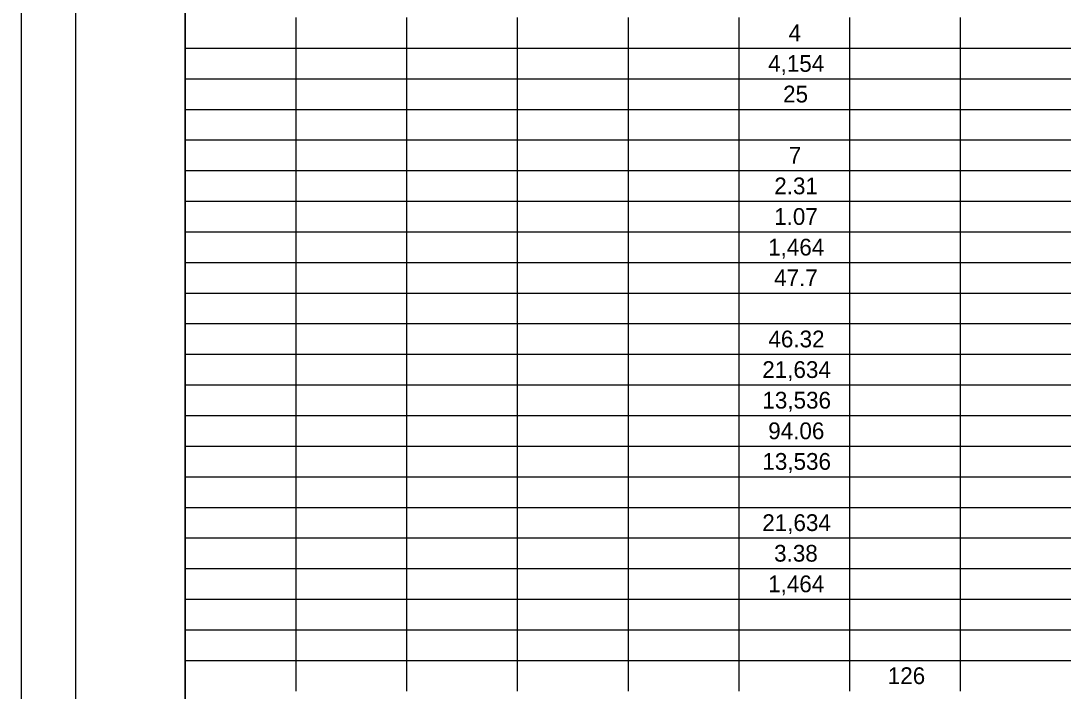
# Model space of a CAD drawing. Extents: x 0 to 34, y 0 to 22.
# Drawn here: x 0 to 9.6, y 9.74 to 15.87 of the extents above; entities that cross this region are included whole.
import ezdxf

# ---------------------------------------------------------------- set-up
doc = ezdxf.new("R2010")
doc.units = 0
for name, color, linetype in [('SH_Border', 7, 'Continuous'), ('SH_Cut_Line', 7, 'Continuous'), ('SH_Text', 7, 'Continuous')]:
    doc.layers.add(name, color=color, linetype=linetype)

msp = doc.modelspace()

# ---------------------------------------------------------------- linework, layer by layer
at = {"layer": 'SH_Border'}
for points in [[(0.5, 21.5), (1.5, 21.5), (1.5, 0.5), (0.5, 0.5)], [(1.5, 21.5), (33.5, 21.5), (33.5, 0.5), (1.5, 0.5)]]:
    msp.add_lwpolyline(points, close=True, dxfattribs=at)
at = {"layer": 'SH_Cut_Line'}
msp.add_lwpolyline([(0, 0), (34, 0), (34, 22), (0, 22)], close=True, dxfattribs=at)
at = {"layer": 'SH_Text'}
for p, q in [((1.5, 15.9), (1.5, 15.62)), ((2.5123, 15.9), (2.5123, 15.62)), ((3.5247, 15.9), (3.5247, 15.62)), ((4.537, 15.9), (4.537, 15.62)), ((5.5494, 15.9), (5.5494, 15.62)), ((6.5617, 15.9), (6.5617, 15.62)), ((7.574, 15.9), (7.574, 15.62)), ((8.5864, 15.9), (8.5864, 15.62)), ((1.5, 15.62), (2.5123, 15.62)), ((1.5, 15.62), (1.5, 15.34)), ((2.5123, 15.62), (3.5247, 15.62)), ((2.5123, 15.62), (2.5123, 15.34)), ((3.5247, 15.62), (4.537, 15.62)), ((3.5247, 15.62), (3.5247, 15.34)), ((4.537, 15.62), (5.5494, 15.62)), ((4.537, 15.62), (4.537, 15.34)), ((5.5494, 15.62), (6.5617, 15.62)), ((5.5494, 15.62), (5.5494, 15.34)), ((6.5617, 15.62), (7.574, 15.62)), ((6.5617, 15.62), (6.5617, 15.34)), ((7.574, 15.62), (8.5864, 15.62)), ((7.574, 15.62), (7.574, 15.34)), ((8.5864, 15.62), (9.5987, 15.62)), ((8.5864, 15.62), (8.5864, 15.34)), ((1.5, 15.34), (2.5123, 15.34)), ((1.5, 15.34), (1.5, 14.78)), ((2.5123, 15.34), (3.5247, 15.34)), ((2.5123, 15.34), (2.5123, 14.78)), ((3.5247, 15.34), (4.537, 15.34)), ((3.5247, 15.34), (3.5247, 14.78)), ((4.537, 15.34), (5.5494, 15.34)), ((4.537, 15.34), (4.537, 14.78)), ((5.5494, 15.34), (6.5617, 15.34)), ((5.5494, 15.34), (5.5494, 14.78)), ((6.5617, 15.34), (7.574, 15.34)), ((6.5617, 15.34), (6.5617, 14.78)), ((7.574, 15.34), (8.5864, 15.34)), ((7.574, 15.34), (7.574, 14.78)), ((8.5864, 15.34), (9.5987, 15.34)), ((8.5864, 15.34), (8.5864, 14.78)), ((1.5, 15.06), (2.5123, 15.06)), ((2.5123, 15.06), (3.5247, 15.06)), ((3.5247, 15.06), (4.537, 15.06)), ((4.537, 15.06), (5.5494, 15.06)), ((5.5494, 15.06), (6.5617, 15.06)), ((6.5617, 15.06), (7.574, 15.06)), ((7.574, 15.06), (8.5864, 15.06)), ((8.5864, 15.06), (9.5987, 15.06)), ((1.5, 14.78), (2.5123, 14.78)), ((1.5, 14.78), (1.5, 14.5)), ((2.5123, 14.78), (3.5247, 14.78)), ((2.5123, 14.78), (2.5123, 14.5)), ((3.5247, 14.78), (4.537, 14.78)), ((3.5247, 14.78), (3.5247, 14.5)), ((4.537, 14.78), (5.5494, 14.78)), ((4.537, 14.78), (4.537, 14.5)), ((5.5494, 14.78), (6.5617, 14.78)), ((5.5494, 14.78), (5.5494, 14.5)), ((6.5617, 14.78), (7.574, 14.78)), ((6.5617, 14.78), (6.5617, 14.5)), ((7.574, 14.78), (8.5864, 14.78)), ((7.574, 14.78), (7.574, 14.5)), ((8.5864, 14.78), (9.5987, 14.78)), ((8.5864, 14.78), (8.5864, 14.5)), ((1.5, 14.5), (2.5123, 14.5)), ((1.5, 14.5), (1.5, 14.22)), ((2.5123, 14.5), (3.5247, 14.5)), ((2.5123, 14.5), (2.5123, 14.22)), ((3.5247, 14.5), (4.537, 14.5)), ((3.5247, 14.5), (3.5247, 14.22)), ((4.537, 14.5), (5.5494, 14.5)), ((4.537, 14.5), (4.537, 14.22)), ((5.5494, 14.5), (6.5617, 14.5)), ((5.5494, 14.5), (5.5494, 14.22)), ((6.5617, 14.5), (7.574, 14.5)), ((6.5617, 14.5), (6.5617, 14.22)), ((7.574, 14.5), (8.5864, 14.5)), ((7.574, 14.5), (7.574, 14.22)), ((8.5864, 14.5), (9.5987, 14.5)), ((8.5864, 14.5), (8.5864, 14.22)), ((1.5, 14.22), (2.5123, 14.22)), ((1.5, 14.22), (1.5, 13.94)), ((2.5123, 14.22), (3.5247, 14.22)), ((2.5123, 14.22), (2.5123, 13.94)), ((3.5247, 14.22), (4.537, 14.22)), ((3.5247, 14.22), (3.5247, 13.94)), ((4.537, 14.22), (5.5494, 14.22)), ((4.537, 14.22), (4.537, 13.94)), ((5.5494, 14.22), (6.5617, 14.22)), ((5.5494, 14.22), (5.5494, 13.94)), ((6.5617, 14.22), (7.574, 14.22)), ((6.5617, 14.22), (6.5617, 13.94)), ((7.574, 14.22), (8.5864, 14.22)), ((7.574, 14.22), (7.574, 13.94)), ((8.5864, 14.22), (9.5987, 14.22)), ((8.5864, 14.22), (8.5864, 13.94)), ((1.5, 13.94), (2.5123, 13.94)), ((1.5, 13.94), (1.5, 11.7)), ((2.5123, 13.94), (3.5247, 13.94)), ((2.5123, 13.94), (2.5123, 11.7)), ((3.5247, 13.94), (4.537, 13.94)), ((3.5247, 13.94), (3.5247, 11.7)), ((4.537, 13.94), (5.5494, 13.94)), ((4.537, 13.94), (4.537, 11.7)), ((5.5494, 13.94), (6.5617, 13.94)), ((5.5494, 13.94), (5.5494, 11.7)), ((6.5617, 13.94), (7.574, 13.94)), ((6.5617, 13.94), (6.5617, 11.7)), ((7.574, 13.94), (8.5864, 13.94)), ((7.574, 13.94), (7.574, 11.7)), ((8.5864, 13.94), (9.5987, 13.94)), ((8.5864, 13.94), (8.5864, 11.7)), ((1.5, 13.66), (2.5123, 13.66)), ((2.5123, 13.66), (3.5247, 13.66)), ((3.5247, 13.66), (4.537, 13.66)), ((4.537, 13.66), (5.5494, 13.66)), ((5.5494, 13.66), (6.5617, 13.66)), ((6.5617, 13.66), (7.574, 13.66)), ((7.574, 13.66), (8.5864, 13.66)), ((8.5864, 13.66), (9.5987, 13.66)), ((1.5, 13.38), (2.5123, 13.38)), ((2.5123, 13.38), (3.5247, 13.38)), ((3.5247, 13.38), (4.537, 13.38)), ((4.537, 13.38), (5.5494, 13.38)), ((5.5494, 13.38), (6.5617, 13.38)), ((6.5617, 13.38), (7.574, 13.38)), ((7.574, 13.38), (8.5864, 13.38)), ((8.5864, 13.38), (9.5987, 13.38)), ((1.5, 13.1), (2.5123, 13.1)), ((2.5123, 13.1), (3.5247, 13.1)), ((3.5247, 13.1), (4.537, 13.1)), ((4.537, 13.1), (5.5494, 13.1)), ((5.5494, 13.1), (6.5617, 13.1)), ((6.5617, 13.1), (7.574, 13.1)), ((7.574, 13.1), (8.5864, 13.1)), ((8.5864, 13.1), (9.5987, 13.1)), ((1.5, 12.82), (2.5123, 12.82)), ((2.5123, 12.82), (3.5247, 12.82)), ((3.5247, 12.82), (4.537, 12.82)), ((4.537, 12.82), (5.5494, 12.82)), ((5.5494, 12.82), (6.5617, 12.82)), ((6.5617, 12.82), (7.574, 12.82)), ((7.574, 12.82), (8.5864, 12.82)), ((8.5864, 12.82), (9.5987, 12.82)), ((1.5, 12.54), (2.5123, 12.54)), ((2.5123, 12.54), (3.5247, 12.54)), ((3.5247, 12.54), (4.537, 12.54)), ((4.537, 12.54), (5.5494, 12.54)), ((5.5494, 12.54), (6.5617, 12.54)), ((6.5617, 12.54), (7.574, 12.54)), ((7.574, 12.54), (8.5864, 12.54)), ((8.5864, 12.54), (9.5987, 12.54)), ((1.5, 12.26), (2.5123, 12.26)), ((2.5123, 12.26), (3.5247, 12.26)), ((3.5247, 12.26), (4.537, 12.26)), ((4.537, 12.26), (5.5494, 12.26)), ((5.5494, 12.26), (6.5617, 12.26)), ((6.5617, 12.26), (7.574, 12.26)), ((7.574, 12.26), (8.5864, 12.26)), ((8.5864, 12.26), (9.5987, 12.26)), ((1.5, 11.98), (2.5123, 11.98)), ((2.5123, 11.98), (3.5247, 11.98)), ((3.5247, 11.98), (4.537, 11.98)), ((4.537, 11.98), (5.5494, 11.98)), ((5.5494, 11.98), (6.5617, 11.98)), ((6.5617, 11.98), (7.574, 11.98)), ((7.574, 11.98), (8.5864, 11.98)), ((8.5864, 11.98), (9.5987, 11.98)), ((1.5, 11.7), (2.5123, 11.7)), ((1.5, 11.7), (1.5, 11.42)), ((2.5123, 11.7), (3.5247, 11.7)), ((2.5123, 11.7), (2.5123, 11.42)), ((3.5247, 11.7), (4.537, 11.7)), ((3.5247, 11.7), (3.5247, 11.42)), ((4.537, 11.7), (5.5494, 11.7)), ((4.537, 11.7), (4.537, 11.42)), ((5.5494, 11.7), (6.5617, 11.7)), ((5.5494, 11.7), (5.5494, 11.42)), ((6.5617, 11.7), (7.574, 11.7)), ((6.5617, 11.7), (6.5617, 11.42)), ((7.574, 11.7), (8.5864, 11.7)), ((7.574, 11.7), (7.574, 11.42)), ((8.5864, 11.7), (9.5987, 11.7)), ((8.5864, 11.7), (8.5864, 11.42)), ((1.5, 11.42), (2.5123, 11.42)), ((1.5, 11.42), (1.5, 10.3)), ((2.5123, 11.42), (3.5247, 11.42)), ((2.5123, 11.42), (2.5123, 10.3)), ((3.5247, 11.42), (4.537, 11.42)), ((3.5247, 11.42), (3.5247, 10.3)), ((4.537, 11.42), (5.5494, 11.42)), ((4.537, 11.42), (4.537, 10.3)), ((5.5494, 11.42), (6.5617, 11.42)), ((5.5494, 11.42), (5.5494, 10.3)), ((6.5617, 11.42), (7.574, 11.42)), ((6.5617, 11.42), (6.5617, 10.3)), ((7.574, 11.42), (8.5864, 11.42)), ((7.574, 11.42), (7.574, 10.3)), ((8.5864, 11.42), (9.5987, 11.42)), ((8.5864, 11.42), (8.5864, 10.3)), ((1.5, 11.14), (2.5123, 11.14)), ((2.5123, 11.14), (3.5247, 11.14)), ((3.5247, 11.14), (4.537, 11.14)), ((4.537, 11.14), (5.5494, 11.14)), ((5.5494, 11.14), (6.5617, 11.14)), ((6.5617, 11.14), (7.574, 11.14)), ((7.574, 11.14), (8.5864, 11.14)), ((8.5864, 11.14), (9.5987, 11.14)), ((1.5, 10.86), (2.5123, 10.86)), ((2.5123, 10.86), (3.5247, 10.86)), ((3.5247, 10.86), (4.537, 10.86)), ((4.537, 10.86), (5.5494, 10.86)), ((5.5494, 10.86), (6.5617, 10.86)), ((6.5617, 10.86), (7.574, 10.86)), ((7.574, 10.86), (8.5864, 10.86)), ((8.5864, 10.86), (9.5987, 10.86)), ((1.5, 10.58), (2.5123, 10.58)), ((2.5123, 10.58), (3.5247, 10.58)), ((3.5247, 10.58), (4.537, 10.58)), ((4.537, 10.58), (5.5494, 10.58)), ((5.5494, 10.58), (6.5617, 10.58)), ((6.5617, 10.58), (7.574, 10.58)), ((7.574, 10.58), (8.5864, 10.58)), ((8.5864, 10.58), (9.5987, 10.58)), ((1.5, 10.3), (2.5123, 10.3)), ((1.5, 10.3), (1.5, 10.02)), ((2.5123, 10.3), (3.5247, 10.3)), ((2.5123, 10.3), (2.5123, 10.02)), ((3.5247, 10.3), (4.537, 10.3)), ((3.5247, 10.3), (3.5247, 10.02)), ((4.537, 10.3), (5.5494, 10.3)), ((4.537, 10.3), (4.537, 10.02)), ((5.5494, 10.3), (6.5617, 10.3)), ((5.5494, 10.3), (5.5494, 10.02)), ((6.5617, 10.3), (7.574, 10.3)), ((6.5617, 10.3), (6.5617, 10.02)), ((7.574, 10.3), (8.5864, 10.3)), ((7.574, 10.3), (7.574, 10.02)), ((8.5864, 10.3), (9.5987, 10.3)), ((8.5864, 10.3), (8.5864, 10.02)), ((1.5, 10.02), (2.5123, 10.02)), ((1.5, 10.02), (1.5, 9.74)), ((2.5123, 10.02), (3.5247, 10.02)), ((2.5123, 10.02), (2.5123, 9.74)), ((3.5247, 10.02), (4.537, 10.02)), ((3.5247, 10.02), (3.5247, 9.74)), ((4.537, 10.02), (5.5494, 10.02)), ((4.537, 10.02), (4.537, 9.74)), ((5.5494, 10.02), (6.5617, 10.02)), ((5.5494, 10.02), (5.5494, 9.74)), ((6.5617, 10.02), (7.574, 10.02)), ((6.5617, 10.02), (6.5617, 9.74)), ((7.574, 10.02), (8.5864, 10.02)), ((7.574, 10.02), (7.574, 9.74)), ((8.5864, 10.02), (9.5987, 10.02)), ((8.5864, 10.02), (8.5864, 9.74))]:
    msp.add_line(p, q, dxfattribs=at)

# ---------------------------------------------------------------- texts
for s, height, p in [('4', 0.1533, (7.0173, 15.6833)), ('4,154', 0.15333, (6.8301, 15.4033)), ('25', 0.15333, (6.9668, 15.1233)), ('7', 0.1533, (7.0191, 14.5633)), ('2.31', 0.15333, (6.8861, 14.2833)), ('1.07', 0.15333, (6.8852, 14.0033)), ('1,464', 0.15333, (6.8301, 13.7233)), ('47.7', 0.15333, (6.8852, 13.4433)), ('46.32', 0.15333, (6.8326, 12.8833)), ('21,634', 0.15333, (6.7764, 12.6033)), ('13,536', 0.15333, (6.7776, 12.3233)), ('94.06', 0.15333, (6.8309, 12.0433)), ('13,536', 0.15333, (6.7776, 11.7633)), ('21,634', 0.15333, (6.7764, 11.2033)), ('3.38', 0.15333, (6.8847, 10.9233)), ('1,464', 0.15333, (6.8301, 10.6433)), ('126', 0.15333, (7.9236, 9.8033))]:
    msp.add_text(s, height=height, dxfattribs=at).set_placement(p)

doc.saveas('drawing.dxf')
